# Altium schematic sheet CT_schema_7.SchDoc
size 287 x 160 mm
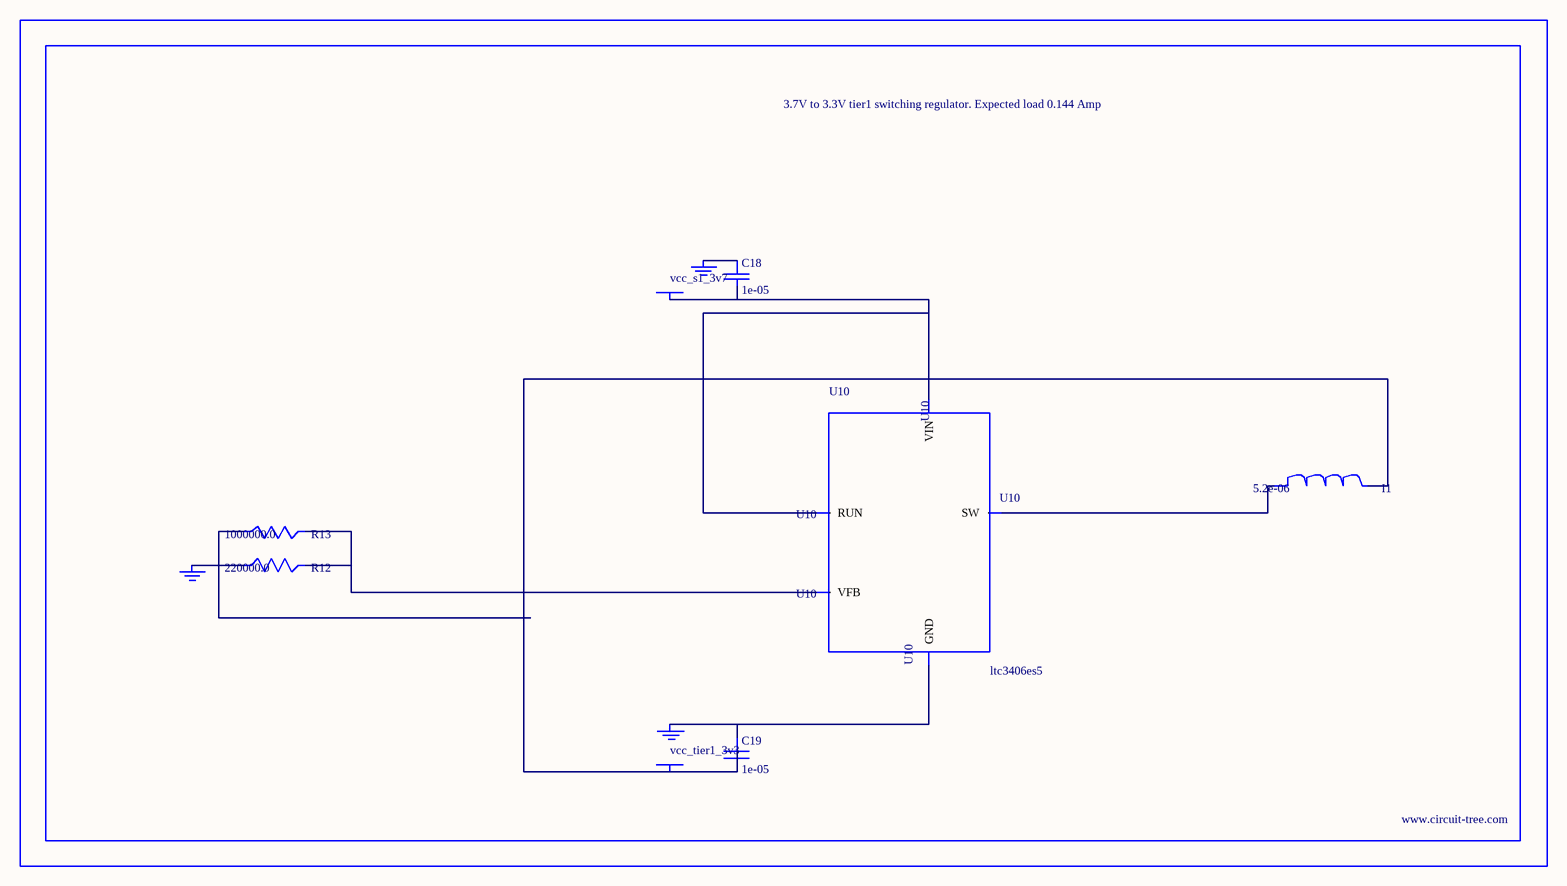
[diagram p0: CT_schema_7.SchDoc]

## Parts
BORDER6  (no value)
C18  1e-05  [C0805]
C19  1e-05  [C0805]
GND_INSTANCE_6_0  (no value)
GND_INSTANCE_6_1  (no value)
GND_INSTANCE_6_2  (no value)
I1  5.2e-06  [DR1040]
POWER_INSTANCE_6_0  vcc_tier1_3v3
POWER_INSTANCE_6_1  vcc_s1_3v7
R12  220000.0  [R0603]
R13  1000000.0  [R0603]
U10  ltc3406es5  [TSOT-23-5]

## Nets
NetC18_1: C18.1 GND_INSTANCE_6_1.0(GND)
NetC18_2: C18.2 POWER_INSTANCE_6_1.0(PWR) U10.1(RUN) U10.4(VIN)
NetC19_1: C19.1 GND_INSTANCE_6_0.0(GND) U10.2(GND)
NetC19_2: C19.2 I1.2 POWER_INSTANCE_6_0.0(PWR) R13.1
NetGND_INSTANCE_6_2_0: GND_INSTANCE_6_2.0(GND) R12.1
NetI1_1: I1.1 U10.3(SW)
NetR12_2: R12.2 R13.2 U10.5(VFB)

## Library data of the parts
BORDER6 = BORDER_PAGE6
C18 C19 = C0805C106K8RACTU
GND_INSTANCE_6_0-GND_INSTANCE_6_2 = GND
I1 = DR1040-5R2-R
POWER_INSTANCE_6_0 POWER_INSTANCE_6_1 = PWR
R12 = RC0603JR-07220KL
R13 = RC0603JR-071ML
